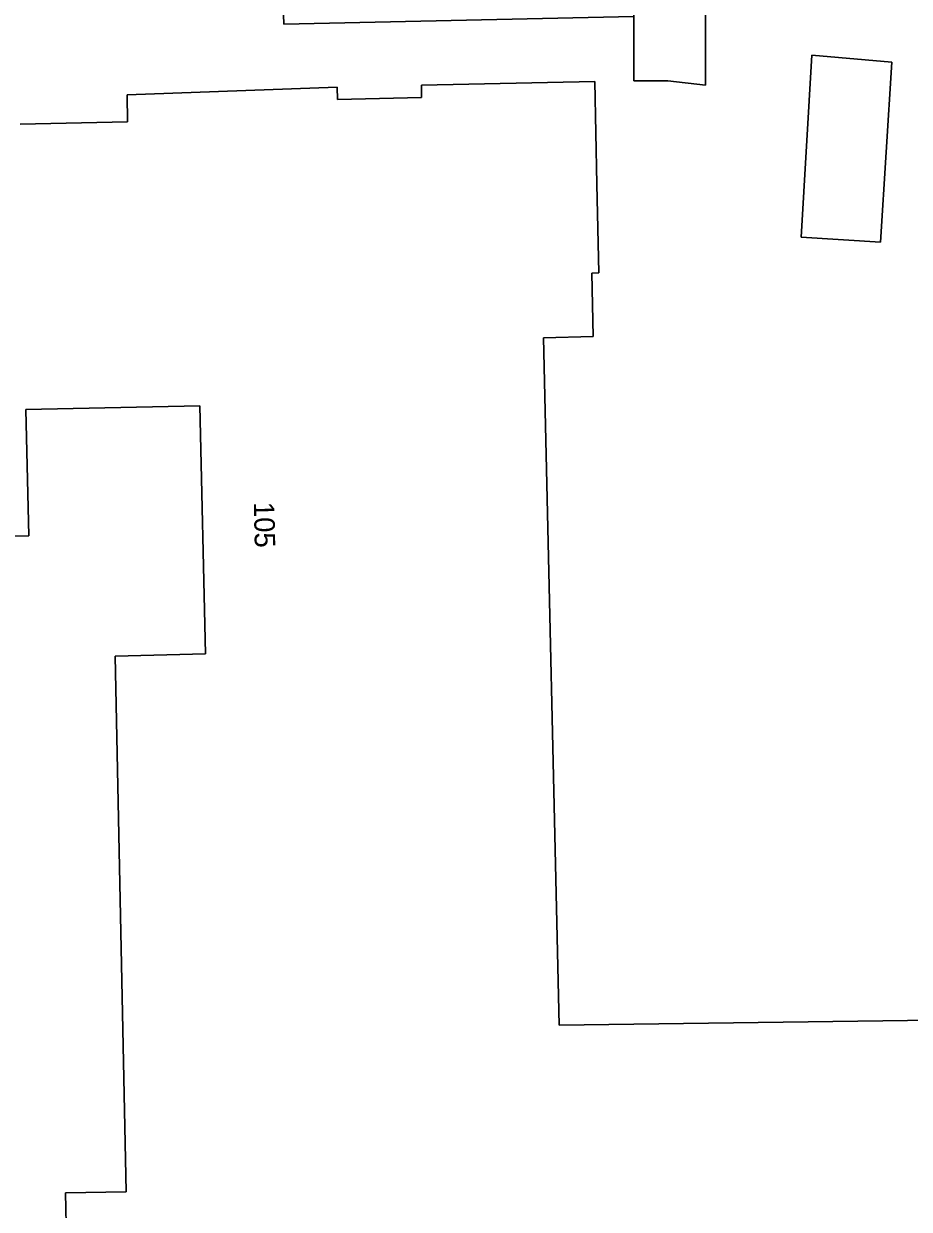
# Model space of a CAD drawing. Extents: x 157320 to 158835, y 386650 to 388491.
# Drawn here: x 157761.4 to 157804.6, y 387812.7 to 387870.6 of the extents above; entities that cross this region are included whole.
import ezdxf

# ---------------------------------------------------------------- set-up
doc = ezdxf.new("R2010")
doc.units = 0
for name, color, linetype in [('IMGEO_Erf', 7, 'Continuous'), ('IMGEO_Gemengd_bos', 7, 'Continuous'), ('IMGEO_Pand', 7, 'Continuous'), ('IMGEO_Pand_nummerreeks', 7, 'Continuous'), ('IMGEO_Voetpad_open', 7, 'Continuous')]:
    doc.layers.add(name, color=color, linetype=linetype)

msp = doc.modelspace()

# ---------------------------------------------------------------- linework, layer by layer
at = {"layer": 'IMGEO_Erf'}
for points in [[(157794.628, 387873.079), (157794.628, 387867.566), (157792.797, 387867.776), (157791.134, 387867.776), (157791.134, 387870.919), (157774.059, 387870.543), (157774.007, 387871.982)], [(157761.201, 387865.653), (157766.439, 387865.77), (157766.409, 387867.096), (157776.667, 387867.471), (157776.68, 387866.87), (157780.781, 387866.957), (157780.768, 387867.557), (157789.226, 387867.736), (157789.331, 387862.738), (157789.423, 387858.398), (157789.093, 387858.391), (157789.159, 387855.292), (157786.725, 387855.24), (157787.494, 387821.679), (157813.002, 387822.024), (157813.23, 387811.054)], [(157763.459, 387811.198), (157763.413, 387813.497), (157766.362, 387813.557), (157765.834, 387839.703), (157770.239, 387839.816), (157769.968, 387851.918), (157761.477, 387851.728), (157761.615, 387845.575), (157753.527, 387845.394)]]:
    msp.add_lwpolyline(points, dxfattribs=at)
msp.add_lwpolyline([(157799.304, 387860.147), (157799.822, 387869.034), (157803.726, 387868.686), (157803.163, 387859.895)], close=True, dxfattribs=at)
at = {"layer": 'IMGEO_Gemengd_bos'}
msp.add_lwpolyline([(157739.416, 387874.598), (157740.621, 387869.428), (157750.238, 387869.454), (157750.201, 387870.784), (157751.067, 387870.808), (157761.038, 387871.083), (157761.056, 387872.053), (157774.007, 387871.982), (157774.059, 387870.543), (157791.134, 387870.919), (157791.122, 387872.809)], close=True, dxfattribs=at)
at = {"layer": 'IMGEO_Pand'}
msp.add_lwpolyline([(157803.163, 387859.895), (157803.726, 387868.686), (157799.822, 387869.034), (157799.304, 387860.147)], close=True, dxfattribs=at)
for points in [[(157813.23, 387811.054), (157813.002, 387822.024), (157787.494, 387821.679), (157786.725, 387855.24), (157789.159, 387855.292), (157789.093, 387858.391), (157789.423, 387858.398), (157789.331, 387862.738), (157789.226, 387867.736), (157780.768, 387867.557), (157780.781, 387866.957), (157776.68, 387866.87), (157776.667, 387867.471), (157766.409, 387867.096), (157766.439, 387865.77), (157761.201, 387865.653)], [(157753.527, 387845.394), (157761.615, 387845.575), (157761.477, 387851.728), (157769.968, 387851.918), (157770.239, 387839.816), (157765.834, 387839.703), (157766.362, 387813.557), (157763.413, 387813.497), (157763.459, 387811.198)]]:
    msp.add_lwpolyline(points, dxfattribs=at)
at = {"layer": 'IMGEO_Voetpad_open'}
msp.add_lwpolyline([(157794.628, 387873.079), (157794.612, 387873.556), (157791.117, 387873.502), (157791.122, 387872.809), (157791.134, 387870.919), (157791.134, 387867.776), (157792.797, 387867.776), (157794.628, 387867.566)], close=True, dxfattribs=at)

# ---------------------------------------------------------------- texts
at = {"layer": 'IMGEO_Pand_nummerreeks'}
msp.add_text('105', height=1, rotation=271.28322, dxfattribs=at).set_placement((157772.594, 387847.211))

doc.saveas('drawing.dxf')
